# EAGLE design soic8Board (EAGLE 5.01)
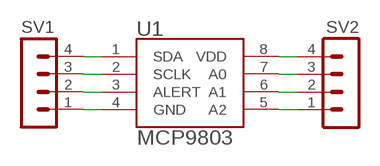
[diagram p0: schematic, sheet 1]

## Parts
SV1  MA04-1  [MA04-1]
SV2  MA04-1  [MA04-1]
U1  MCP9803  [SO-08M]

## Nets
N$1: SV1.4 U1.1(SDA)
N$2: SV1.3 U1.2(SCLK)
N$3: SV1.2 U1.3(ALERT)
N$4: SV1.1 U1.4(GND)
N$5: SV2.4 U1.8(VDD)
N$6: SV2.3 U1.7(A0)
N$7: SV2.2 U1.6(A1)
N$8: SV2.1 U1.5(A2)

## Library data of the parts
SV1 SV2 = con-lstb:MA04-1: PIN HEADER
U1 = marios:MCP9803: MCP9803 2 Wire Temperature Sensor Microchip MCP9803 2 Wire High Accuracy Temperature Sensor http://ww1.microchip.com/downloads/en/DeviceDoc/21909b.pdf

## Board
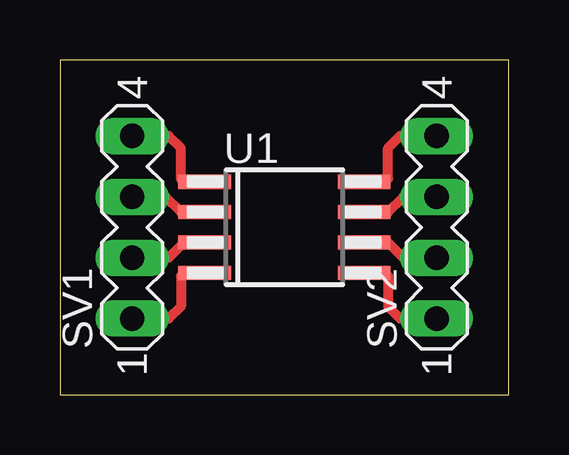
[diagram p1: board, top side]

Size 18.72 x 13.96 mm. Coordinates in mm from the lower left corner, seen from the top.
Outline: 0,0 18.72,0 18.72,13.96 0,13.96 0,0
Copper layers (1*16): Top 0.035mm / dielectric 1.5mm / Bottom 0.035mm
Design rules "default": minimum track width 10mil, minimum drill 24mil, track to track 8mil, track to pad 8mil, pad to pad 8mil, via to via 8mil, smd to smd 8mil, copper to edge 40mil, drill to drill 8mil, minimum pad ring 10mil, minimum via ring 8mil, stop-mask expansion 4mil, vias tented up to drill 0mil, thermal gap 10mil

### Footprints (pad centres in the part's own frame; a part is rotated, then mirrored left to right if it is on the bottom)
MA04-1 = drill 1.016 long: 1 -3.81,0; 2 -1.27,0; 3 1.27,0; 4 3.81,0
SO-08M = smd 0.6 x 2.2: 1 -1.905,-3.33; 2 -0.635,-3.33; 3 0.635,-3.33; 4 1.905,-3.33; 5 1.905,3.33; 6 0.635,3.33; 7 -0.635,3.33; 8 -1.905,3.33

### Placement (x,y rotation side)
SV1  3.01,6.98 90 top
SV2  15.71,6.98 90 top
U1  9.36,6.98 270 top

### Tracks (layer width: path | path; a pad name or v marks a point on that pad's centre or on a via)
N$1
  Top 0.406: U1.1 5.17,8.88 5.04,9.01 5.04,10.28 4.53,10.79 SV1.4
N$2
  Top 0.406: U1.2 5.04,7.62 4.41,8.25 SV1.3
N$3
  Top 0.406: U1.3 5.17,6.35 4.53,5.71 SV1.2
N$4
  Top 0.406: U1.4 5.17,5.07 5.04,4.95 5.04,3.68 4.53,3.17 SV1.1
N$5
  Top 0.406: U1.8 13.55,8.88 13.68,9.01 13.68,10.28 14.19,10.79 SV2.4
N$6
  Top 0.406: U1.7 13.68,7.62 14.31,8.25 SV2.3
N$7
  Top 0.406: U1.6 13.68,6.35 14.31,5.71 SV2.2
N$8
  Top 0.406: U1.5 13.55,5.07 13.68,4.95 13.68,3.68 14.19,3.17 SV2.1 15.96,3.17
